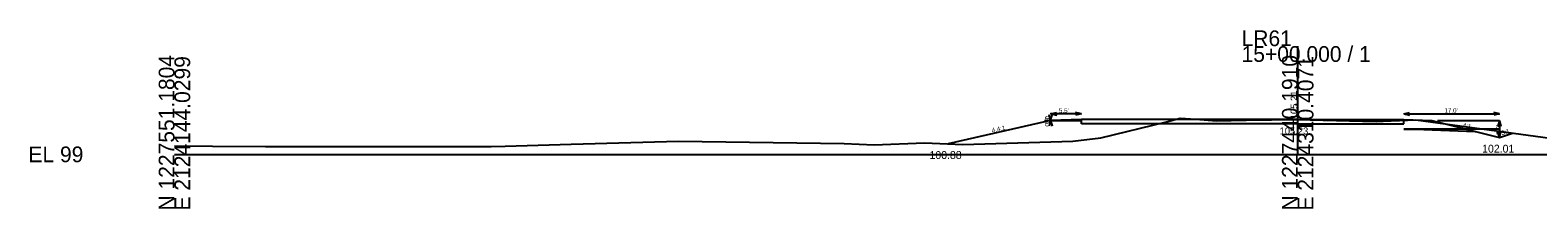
# Model space of a CAD drawing. Extents: x -26 to 1403, y -10 to 9574.
# Drawn here: x 974.3 to 1242.8, y 4990.3 to 5022.1 of the extents above; entities that cross this region are included whole.
import ezdxf

# ---------------------------------------------------------------- set-up
doc = ezdxf.new("R2010")
doc.units = 0
for name, color, linetype in [('XS_CELL', 7, 'Continuous'), ('XS_P_FINISHED_GRADE', 7, 'Continuous'), ('XS_P_FINISHED_GRADE_ELEV_TX', 7, 'Continuous'), ('XS_P_SUBGRADE_GRANULAR', 7, 'Continuous'), ('XS_P_SUBGRADE_PAVEMENT', 7, 'Continuous'), ('XS_P_TX_CLEARZONE', 7, 'Continuous'), ('XS_P_TX_DCH', 7, 'Continuous'), ('XS_P_TX_FS_BS', 7, 'Continuous'), ('XS_X_GROUND', 7, 'Continuous'), ('XS_X_GROUND_TX', 7, 'Continuous')]:
    doc.layers.add(name, color=color, linetype=linetype)

msp = doc.modelspace()

# ---------------------------------------------------------------- linework, layer by layer
at = {"layer": 'XS_CELL'}
for p, q in [((1200, 5000), (1200, 5019.26)), ((1000, 5000), (1200, 5000)), ((1200, 5000), (1400, 5000))]:
    msp.add_line(p, q, dxfattribs=at)
at = {"layer": 'XS_P_FINISHED_GRADE'}
for p, q in [((1156.01, 5006.01), (1137.74, 5001.88)), ((1161.53, 5006.21), (1156.01, 5006.01)), ((1200, 5006.21), (1161.53, 5006.21)), ((1200, 5006.21), (1218.9, 5006.21)), ((1218.9, 5006.21), (1223.9, 5006.01)), ((1223.9, 5006.01), (1235.9, 5003.01)), ((1235.9, 5003.01), (1238.26, 5003.8))]:
    msp.add_line(p, q, dxfattribs=at)
at = {"layer": 'XS_P_SUBGRADE_GRANULAR'}
for p, q in [((1155.79, 5006.01), (1161.53, 5006.01)), ((1161.53, 5006.01), (1159.53, 5006.01)), ((1236.1, 5004.51), (1218.9, 5004.51)), ((1218.9, 5004.51), (1220.9, 5004.51)), ((1220.9, 5004.51), (1231.61, 5004.08))]:
    msp.add_line(p, q, dxfattribs=at)
at = {"layer": 'XS_P_SUBGRADE_PAVEMENT'}
for p, q in [((1161.53, 5005.46), (1161.53, 5006.21)), ((1200, 5005.46), (1161.53, 5005.46)), ((1200, 5005.46), (1218.9, 5005.46)), ((1218.9, 5005.46), (1218.9, 5006.21))]:
    msp.add_line(p, q, dxfattribs=at)
at = {"layer": 'XS_P_TX_CLEARZONE'}
for p, q in [((1156.01, 5006.01), (1155.73, 5007.01)), ((1156.01, 5007.21), (1157.12, 5007.46)), ((1156.01, 5007.21), (1157.12, 5006.96)), ((1161.53, 5007.21), (1156.01, 5007.21)), ((1156.01, 5006.01), (1156.29, 5007.01)), ((1161.53, 5007.21), (1160.42, 5007.46)), ((1161.53, 5007.21), (1160.42, 5006.96)), ((1218.9, 5007.21), (1219.9, 5007.46)), ((1218.9, 5007.21), (1219.9, 5006.96)), ((1218.9, 5007.21), (1235.9, 5007.21)), ((1235.9, 5007.21), (1234.9, 5007.46)), ((1235.9, 5007.21), (1234.9, 5006.96)), ((1154.9, 5006.01), (1156.01, 5006.01)), ((1156.01, 5006.01), (1155.73, 5005.01)), ((1156.01, 5006.01), (1156.29, 5005.01)), ((1224.9, 5006.01), (1235.9, 5006.01)), ((1235.9, 5006.01), (1235.65, 5005.01)), ((1235.9, 5003.01), (1235.65, 5004.01)), ((1235.9, 5006.01), (1235.9, 5003.01)), ((1235.9, 5006.01), (1236.15, 5005.01)), ((1235.9, 5003.01), (1236.15, 5004.01))]:
    msp.add_line(p, q, dxfattribs=at)
at = {"layer": 'XS_X_GROUND'}
for p, q in [((1164.95, 5002.93), (1176.63, 5005.78)), ((1176.63, 5005.78), (1179.08, 5006.42)), ((1179.08, 5006.42), (1181.85, 5006.24)), ((1181.85, 5006.24), (1185.55, 5005.99)), ((1185.55, 5005.99), (1190.82, 5006.07)), ((1190.82, 5006.07), (1199.9, 5006.23)), ((1199.9, 5006.23), (1211.53, 5005.9)), ((1211.53, 5005.9), (1213.94, 5005.83)), ((1213.94, 5005.83), (1215.2, 5005.88)), ((1215.2, 5005.88), (1221.02, 5006.15)), ((1221.02, 5006.15), (1249.14, 5002.31)), ((1000, 5001.52), (1006.79, 5001.47)), ((1006.79, 5001.47), (1016.23, 5001.41)), ((1016.23, 5001.41), (1033.85, 5001.4)), ((1033.85, 5001.4), (1056.4, 5001.39)), ((1056.4, 5001.39), (1058.89, 5001.46)), ((1058.89, 5001.46), (1070.66, 5001.82)), ((1070.66, 5001.82), (1089.72, 5002.33)), ((1089.72, 5002.33), (1119.25, 5001.92)), ((1119.25, 5001.92), (1124.56, 5001.71)), ((1124.56, 5001.71), (1133.55, 5002.08)), ((1133.55, 5002.08), (1140.37, 5001.76)), ((1140.37, 5001.76), (1159.97, 5002.34)), ((1159.97, 5002.34), (1164.95, 5002.93))]:
    msp.add_line(p, q, dxfattribs=at)

# ---------------------------------------------------------------- texts
at = {"layer": 'XS_CELL'}
for s, p in [('LR61', (1190, 5019.26)), ('15+00.000 / 1', (1190, 5016.46)), ('EL 99', (974, 4998.6))]:
    msp.add_text(s, height=2.8, dxfattribs=at).set_placement(p)
for s, p in [('N 1227551.1804', (1000, 4990)), ('E 2124144.0299', (1002.8, 4990)), ('N 1227440.1910', (1200, 4990)), ('E 2124310.4071', (1202.8, 4990))]:
    msp.add_text(s, height=2.8, rotation=90, dxfattribs=at).set_placement(p)
at = {"layer": 'XS_P_FINISHED_GRADE_ELEV_TX'}
msp.add_text('105.21', height=1.25, rotation=90, dxfattribs=at).set_placement((1199.98, 5006.25))
at = {"layer": 'XS_P_TX_CLEARZONE'}
for s, p in [("0.0'", (1155.79, 5004.95)), ("3.0'", (1236.1, 5003.48))]:
    msp.add_text(s, height=0.8, rotation=90, dxfattribs=at).set_placement(p)
for s, p in [("5.5'", (1157.48, 5007.41)), ("17.0'", (1226.12, 5007.41))]:
    msp.add_text(s, height=0.8, dxfattribs=at).set_placement(p)
at = {"layer": 'XS_P_TX_DCH'}
for s, p in [('102.01', (1232.84, 5000.31)), ('100.88', (1134.44, 4999.18))]:
    msp.add_text(s, height=1.4, dxfattribs=at).set_placement(p)
at = {"layer": 'XS_P_TX_FS_BS'}
for s, rotation, p in [('1:0', 90, (1155.81, 5005.29)), ('4.4:1', 12.7155, (1145.61, 5003.86)), ('4:1', 345.9638, (1229.29, 5004.87)), ('3:1', 18.4349, (1236.37, 5003.38))]:
    msp.add_text(s, height=0.8, rotation=rotation, dxfattribs=at).set_placement(p)
at = {"layer": 'XS_X_GROUND_TX'}
msp.add_text('105.23', height=1.25, rotation=360, dxfattribs=at).set_placement((1196.77, 5003.54))

doc.saveas('drawing.dxf')
